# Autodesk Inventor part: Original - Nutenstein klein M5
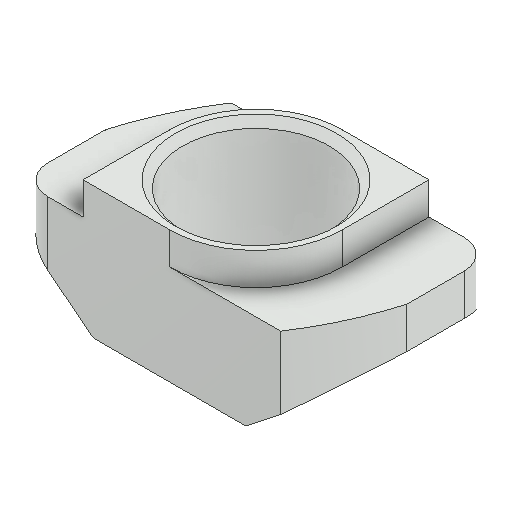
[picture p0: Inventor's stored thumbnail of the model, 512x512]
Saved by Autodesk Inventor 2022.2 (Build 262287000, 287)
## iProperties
Created: 2024-09
Part Number: Original - Nutenstein klein M5
Material: Generico
Document SubType Name: Modeling
Designer: 18907419
Density: 1 g/cm^3
Appearance: Default
Author: 18907419
Revision Number: ANY
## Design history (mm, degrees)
feature "Verrundung1"
node "Solido1"
